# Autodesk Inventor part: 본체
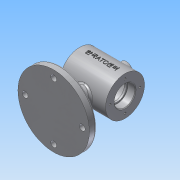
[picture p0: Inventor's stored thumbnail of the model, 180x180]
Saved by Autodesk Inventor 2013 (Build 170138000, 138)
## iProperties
Created: 2018-12
Part Number: 본체
Material: 알루미늄 6061
Document SubType Name: Modeling
Designer: Administrator
Density: 2.71 g/cm^3
Mass: 687.627 g
Surface Area: 555.481 cm^2
Volume: 253.737 cm^3
Author: Administrator
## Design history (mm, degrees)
sketch "스케치1"
  geometry: C1 r 30 at (0, 0); 1 further point
  constraints: 1 centre point, 1 coincident
  dimensions: "d0" = 60 diameter of C1
extrude "돌출1" new body sketch "스케치1" distance "d1" = 70; taper "d2" = 0 deg
sketch "스케치2"
  geometry: L1 (0, 30)-(70, 30) reference; L2 (70, 30)-(70, -30) reference; L3 (70, -30)-(0, -30) reference; L4 (0, -30)-(0, 30) reference; L5 (0, 16)-(12, 16); L6 (12, 16)-(12, 14); L7 (12, 14)-(15, 14); L8 (15, 14)-(15, 25); L9 (15, 25)-(55, 25); L10 (55, 25)-(55, 14); L11 (55, 14)-(58, 14); L12 (58, 14)-(58, 16); L13 (58, 16)-(70, 16); L14 (0, 0)-(70, 0); L15 (0, 30)-(70, 30) reference; L16 (70, 30)-(70, -30) reference; L17 (70, -30)-(0, -30) reference; L18 (0, -30)-(0, 30) reference
  constraints: 20 end point, 6 parallel, 3 perpendicular, 2 collinear, 2 point on line, 1 midpoint
  dimensions: "d3" = 32 diameter of L13 L14; "d5" = 12 distance of L12.end L13.end; "d6" = 12 distance of L5.start L5.end; "d7" = 28 diameter of L11 L14; "d8" = 3 distance of L10.end L11.end; "d9" = 3 distance of L6.end L7.end; "d10" = 50 diameter of L9 L14; "d11" = 40 distance of L8.end L9.end (derived)
revolve "회전1" sketch "스케치2" stored, may be unused: angle "d12" = 90 deg
sketch "스케치3"
  geometry: C1 r 16 at (0, 0) reference; 2 further points
  constraints: 1 vertical alignment
  dimensions: "d13" = 23 distance of point (0, 23) point (0, 0)
hole "구멍1" sketch "스케치3" at (0, 23) diameter "d14" = 3.242; stored, may be unused: countersink angle "d18" = 90 deg, drill point angle "d20" = 118 deg; dims "d15" = 8, "d16" = 4, "d17" = 2, "d19" = 10
node "작업 평면1"
node "작업 평면2"
node "작업 평면3"
sketch "스케치8"
  geometry: L1 (0, -30)-(0, 30) reference; C1 r 55 at (-35, 0); 1 further point
  constraints: 1 centre point, 1 horizontal alignment
  dimensions: "d31" = 110 diameter of C1; "d32" = 35 distance from line of C1.centre L1
extrude "돌출3" join sketch "스케치8" distance "d33" = 11; taper "d34" = 0 deg
sketch "스케치10"
  geometry: C1 r 55 at (0, 0) reference; 1 further point
extrude "돌출4" join sketch "스케치10" distance "d35" = 15; taper "d36" = -75 deg
sketch "스케치11"
  geometry: C1 r 55 at (0, 0) reference; C2 r 12 at (0, 0); 2 further points
  constraints: 1 centre point, 1 coincident
  dimensions: "d37" = 24 diameter of C2
extrude "돌출5" join sketch "스케치11" stored distance "d38" = 15; taper "d39" = 0 deg
fillet "모깎기2" dims "d40" = 3
node "작업 평면4"
sketch "스케치15"
  geometry: L1 (-35, 30)-(-35, -30) reference; C1 r 10 at (0, 0); 1 further point
  constraints: 1 centre point, 1 horizontal alignment
  dimensions: "d44" = 20 diameter of C1; "d45" = 35 distance from line of C1.centre L1
extrude "돌출6" join sketch "스케치15" stored distance "d46" = 15; taper "d47" = 0 deg
sketch "스케치16"
  geometry: C1 r 10 at (0, 0) reference; C2 r 5 at (0, 0); 1 further point
  constraints: 1 centre point, 1 coincident
  dimensions: "d48" = 10 diameter of C2
extrude "돌출7" cut sketch "스케치16" stored distance "d49" = 15; taper "d50" = 0 deg
sketch "스케치17"
  geometry: C1 r 55 at (0, 0) reference; 2 further points
  constraints: 1 vertical alignment
  dimensions: "d51" = 44 distance of point (0, -44) C1.centre
hole "구멍2" sketch "스케치17" at (0, -44) diameter "d52" = 9; stored, may be unused: countersink angle "d56" = 90 deg, drill point angle "d58" = 118 deg; dims "d53" = 8, "d54" = 14, "d55" = 2, "d57" = 10
node "작업 평면5"
sketch "스케치18"
  geometry: C1 r 4.5 at (0, -44) reference; C2 r 55 at (0, 0) reference; 2 further points
  constraints: 1 coincident
hole "구멍3" sketch "스케치18" at (0, -44) diameter "d60" = 14; stored, may be unused: countersink angle "d64" = 90 deg, drill point angle "d66" = 118 deg; dims "d61" = 8, "d62" = 14, "d63" = 2, "d65" = 10
node "작업 평면6"
sketch "스케치19"
  geometry: L1 (0, 30)-(0, -30) reference; L2 (0, 30)-(70, 30) reference; 2 further points
  constraints: 1 other
  dimensions: "d71" = 35 distance from line of point (35, 0) L1; "d72" = 30 distance from line of point (35, 0) L2
feature "엠보싱1" sketch "스케치19" dims "d73" = 0.5, "d74" = 0
chamfer "모따기1" distance "d75" = 1; stored, may be unused: second distance "d76" = 2, angle "d77" = 45 deg
fillet "모깎기3" dims "d78" = 3
fillet "모깎기4" dims "d79" = 0.3
node "솔리드1"
pattern_circular "원형 패턴1" dims angle "d22" = 360 deg
mirror "대칭1"
pattern_circular "원형 패턴2" dims angle "d68" = 360 deg
node "투영된 루프1"
node "투영된 루프2"
node "투영된 루프5"
node "투영된 루프6"
node "투영된 루프7"
node "절단 모서리 투영1"
node "절단 모서리 투영2"
other parameters: "d24" = -75, "d30" = -75, "d43" = -112, "d70" = 80.5
